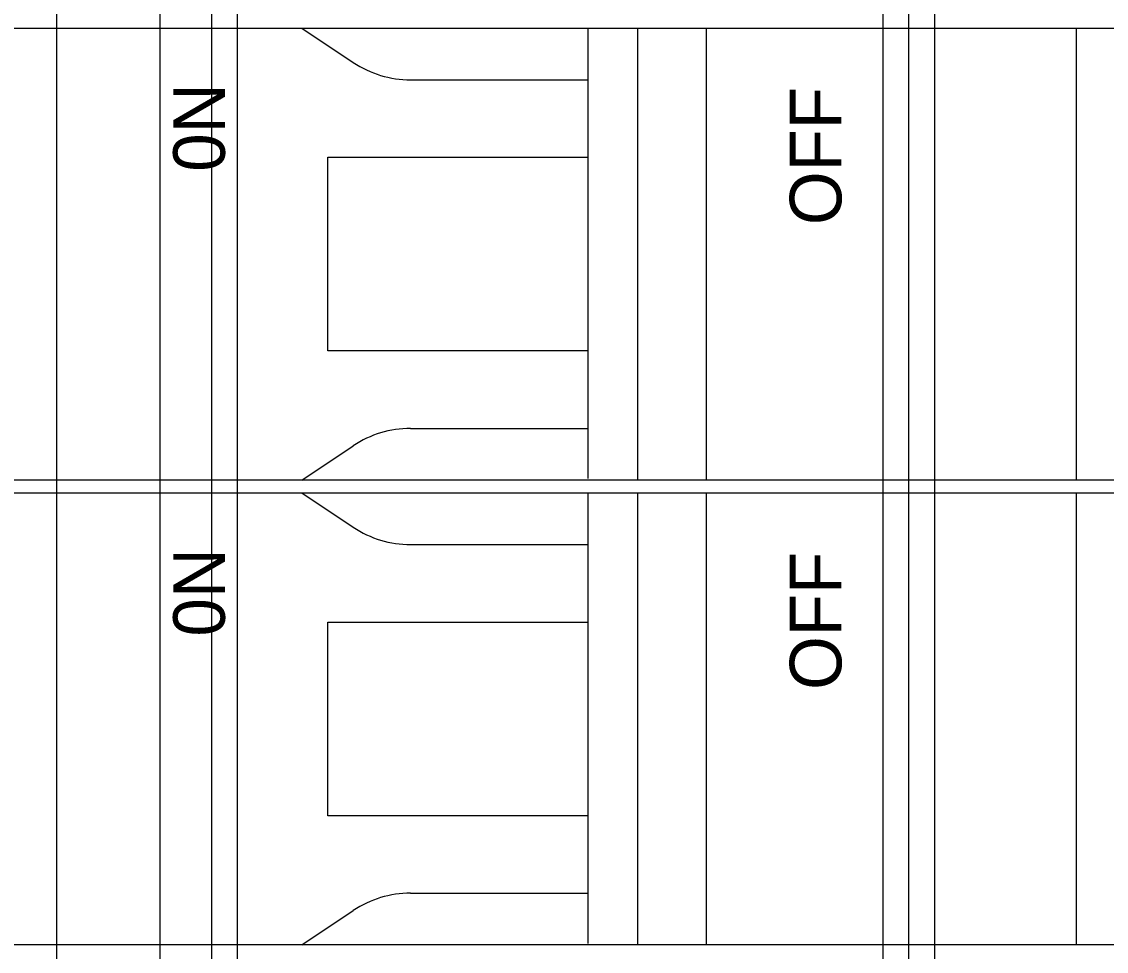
# Model space of a CAD drawing. Extents: x 0 to 4205, y 0 to 2970.
# Drawn here: x 935.66 to 977.67, y 1137.34 to 1173.34 of the extents above; entities that cross this region are included whole.
import ezdxf

# ---------------------------------------------------------------- set-up
doc = ezdxf.new("R2010")
doc.units = 0
doc.layers.add('Level 1', color=7, linetype='Continuous')

# ---------------------------------------------------------------- blocks, each defined once
blk = doc.blocks.new('NCX-2418-3U')
for p, q in [((-204, 132.85), (-204, -99.15)), ((-203, 132.85), (-203, -99.15)), ((-178, 132.85), (-178, -99.15)), ((-177, 132.85), (-177, -99.15)), ((-176, 132.85), (-176, -99.15)), ((-210, 124.85), (-210, -91.15)), ((-206, 124.85), (-206, -91.15))]:
    blk.add_line(p, q)

msp = doc.modelspace()

# ---------------------------------------------------------------- linework, layer by layer
at = {"layer": 'Level 1'}
for p, q in [((914.008, 1173.093), (997.008, 1173.093)), ((946.508, 1173.093), (948.5, 1171.765)), ((957.592, 1155.65), (957.592, 1173.069)), ((959.508, 1173.093), (959.508, 1155.593)), ((962.161, 1173.093), (962.161, 1155.593)), ((976.508, 1155.593), (976.508, 1173.093)), ((950.719, 1171.093), (957.592, 1171.093)), ((947.508, 1160.593), (947.508, 1168.093)), ((947.508, 1168.093), (957.592, 1168.093)), ((957.592, 1160.593), (947.508, 1160.593)), ((950.719, 1157.593), (957.592, 1157.593)), ((946.508, 1155.593), (948.5, 1156.921)), ((997.008, 1155.593), (914.008, 1155.593)), ((914.008, 1155.093), (997.008, 1155.093)), ((946.508, 1155.093), (948.5, 1153.765)), ((957.592, 1137.65), (957.592, 1155.069)), ((959.508, 1155.093), (959.508, 1137.593)), ((962.161, 1155.093), (962.161, 1137.593)), ((976.508, 1137.593), (976.508, 1155.093)), ((950.719, 1153.093), (957.592, 1153.093)), ((947.508, 1142.593), (947.508, 1150.093)), ((947.508, 1150.093), (957.592, 1150.093)), ((957.592, 1142.593), (947.508, 1142.593)), ((950.719, 1139.593), (957.592, 1139.593)), ((946.508, 1137.593), (948.5, 1138.921)), ((997.008, 1137.593), (914.008, 1137.593))]:
    msp.add_line(p, q, dxfattribs=at)
for points in [[(914.008, 1155.593), (914.008, 1173.093), (997.008, 1173.093), (997.008, 1155.593)], [(914.008, 1155.593), (914.008, 1173.093), (997.008, 1173.093), (997.008, 1155.593)], [(914.008, 1137.593), (914.008, 1155.093), (997.008, 1155.093), (997.008, 1137.593)], [(914.008, 1137.593), (914.008, 1155.093), (997.008, 1155.093), (997.008, 1137.593)]]:
    msp.add_lwpolyline(points, close=True, dxfattribs=at)
for centre, start, end in [((950.719, 1175.093), 236.3099, 270), ((950.719, 1153.593), 90, 123.6901), ((950.719, 1157.093), 236.3099, 270), ((950.719, 1135.593), 90, 123.6901)]:
    msp.add_arc(centre, 4, start, end, dxfattribs=at)

# ---------------------------------------------------------------- block references
msp.add_blockref('NCX-2418-3U', (1147.008, 1066.693))

# ---------------------------------------------------------------- texts
for s, p in [('0N', (943.525, 1167.532)), ('OFF', (967.406, 1165.466)), ('0N', (943.525, 1149.532)), ('OFF', (967.406, 1147.466))]:
    msp.add_text(s, height=2, rotation=90, dxfattribs=at).set_placement(p)

doc.saveas('drawing.dxf')
